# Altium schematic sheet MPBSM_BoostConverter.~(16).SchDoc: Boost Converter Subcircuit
size A3; Date: Not shown in title block; ApprovedBy: Not shown in title block; CheckedBy: Not shown in title block; Author: Not shown in title block; CompanyName: Not shown in title block; DrawnBy: Not shown in title block; Engineer: Not shown in title block; Organization: Not shown in title block; Address1: Not shown in title block; Address2: Not shown in title block; Address3: Not shown in title block; Address4: Not shown in title block; DocumentNumber: 4; Revision: Use project parameter SCH_Rev; SheetNumber: 4; SheetTotal: 12; PageSetup: Record=PageOptions¦CenterHorizontal=True¦CenterVertical=True¦PrintScale=0.69¦XCorrection=1.00¦YCorrection=1.00¦PrintKind=0¦BorderSize=5000000¦LeftOffset=0¦BottomOffset=0¦Orientation=2¦PaperLength=1000¦PaperWidth=1000¦Scale=100¦PaperSource=15¦PrintQuality=600¦MediaType=1¦DitherType=10¦PaperKind=Letter¦PrintScaleMode=1
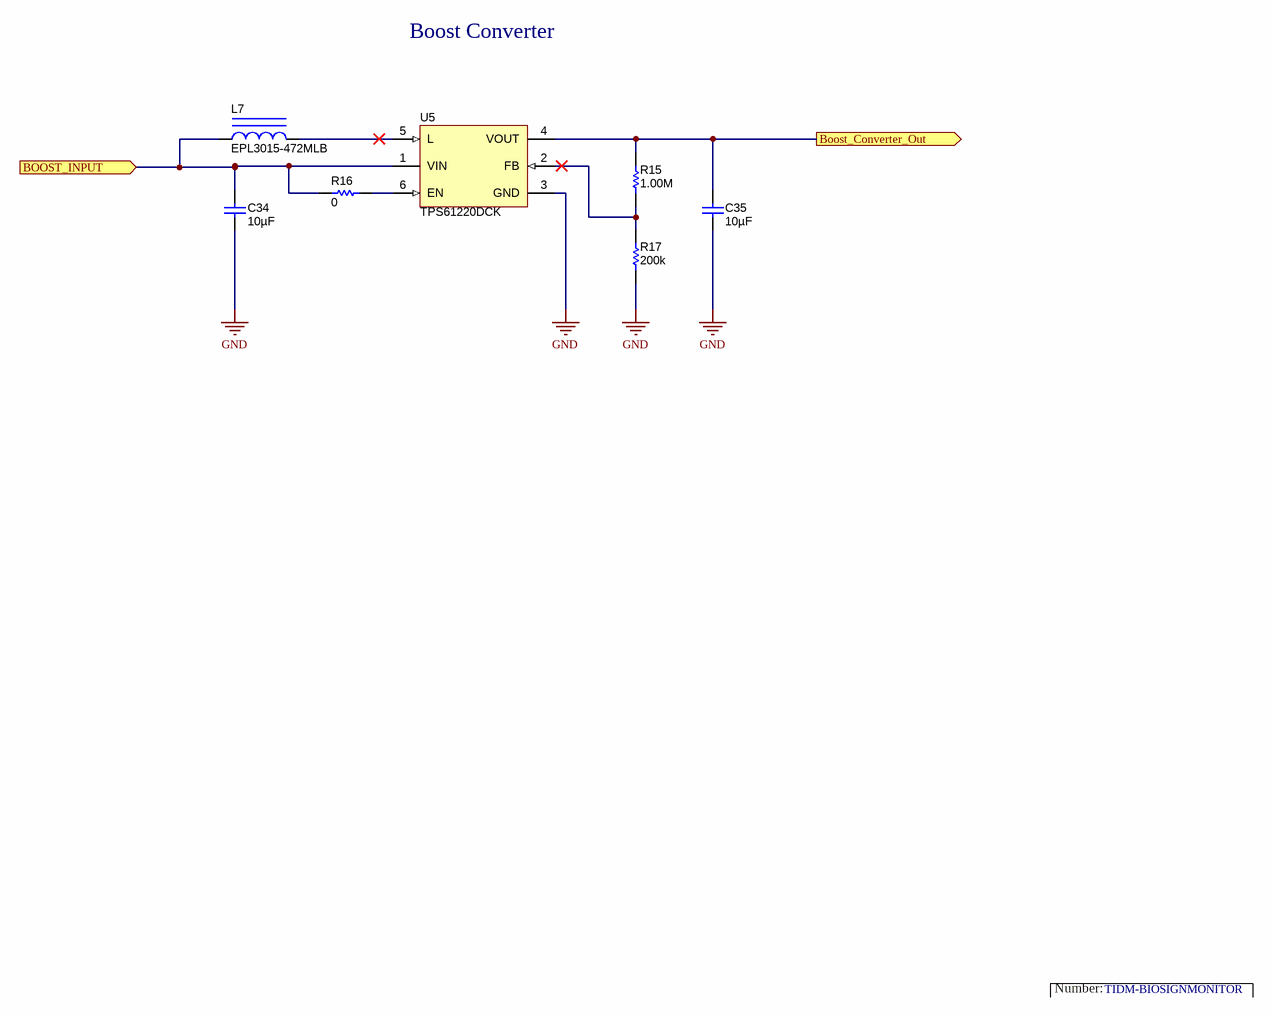
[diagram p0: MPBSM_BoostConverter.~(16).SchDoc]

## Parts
C34  ValueDisplayed: 10µF  [0402]  (hidden comment: CL05A106MQ5NUNC)
C35  ValueDisplayed: 10µF  [0402]  (hidden comment: CL05A106MQ5NUNC)
L7  EPL3015-472MLB  [EPL3015]
R15  ValueDisplayed: 1.00M  [0402]  (hidden comment: ERJ-2RKF1004X)
R16  ValueDisplayed: 0  [0402]  (hidden comment: ERJ-2GE0R00X)
R17  ValueDisplayed: 200k  [0402]  (hidden comment: ERJ-2RKF2003X)
U5  TPS61220DCK  [DCK0006A_N]

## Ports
Boost_Converter_Out (out), BOOST_INPUT (in)

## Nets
GND: C34.2 C35.2 R17.1 U5.3(GND)
Boost_Converter_Out: C35.1 R15.2 U5.4(VOUT) ; port Boost_Converter_Out
BOOST_INPUT: C34.1 L7.1 R16.1 U5.1(VIN) ; port BOOST_INPUT
NetL7_2: L7.2 U5.5(L)
NetR15_1: R15.1 R17.2 U5.2(FB)
NetR16_2: R16.2 U5.6(EN)

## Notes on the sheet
- Boost Converter
- Number:
- TIDM-BIOSIGNMONITOR

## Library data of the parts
C34 C35 = CL05A106MQ5NUNC: CAP, CERM, 10 µF, 6.3 V, +/- 20%, X5R, 0402; Manufacturer: Samsung; Polarized: N; CompType: Capacitor; Value: 10uF; U/M: EA; Cap_F: 0.00001; Tolerance_%: 20; Value1: Unknown; VDC_V: 6.3; Value2: 6.3V; TaMin_C: -55; TaMax_C: 85
L7 = EPL3015-472MLB: Inductor, Shielded, Ferrite, 4.7uH, 1.2A, 0.14 ohm, SMD; Manufacturer: Coilcraft; Ind_H: 4.7E-6; ValueDisplayed: 4.7µH; Imax_A: 1.2; Irms: 1.4A @ 40C rise; Isat: 1.2A @ 30% inductance drop; DCR_ohm: 0.14
R15 = ERJ-2RKF1004X: RES, 1.00 M, 1%, 0.1 W, 0402; Manufacturer: Panasonic; CompType: Resistor; Value: 1.00Meg; Res_ohm: 1000000; Value_Code: 1M00; Tolerance_%: 1; Power_W: 0.1; Value2: 0.1W; VDC_V: 50; TempCo: 100 ppm/C; EIA_Code: E96; U/M: EA
R16 = ERJ-2GE0R00X: RES, 0, 5%, 0.063 W, 0402; Manufacturer: Panasonic; CompType: Resistor; Value: 0; Value_Code: 0000; Tolerance_%: 5; Power_W: 0.063; Value2: 0.063W; VDC_V: 50; TempCo: 600 ppm/C; EIA_Code: E24; U/M: EA
R17 = ERJ-2RKF2003X: RES, 200 k, 1%, 0.1 W, 0402; Manufacturer: Panasonic; CompType: Resistor; Value: 200k; Res_ohm: 200000; Tolerance_%: 1; Power_W: 0.1; Value2: 0.1W; VDC_V: 50; TempCo: 100 ppm/C; EIA_Code: E96; U/M: EA
U5 = TPS61220DCK: LOW INPUT VOLTAGE STEP-UP CONVERTER IN 6 PIN SC-70 PACKAGE, DCK0006A; Manufacturer: Texas Instruments; SymbolCreator: a0799628; CompType: IC; U/M: EA; Value: Analog; Value1: 0.7 V to 5.5 V; Value2: 200 mA; TaMax_C: -40°C; TaMin_C: 125°C; InputVoltageMin_V: 0.7 V; InputVoltageMax_V: 5.5 V; SwitchingFrequency: 2 MHz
